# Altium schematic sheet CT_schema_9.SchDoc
size 254 x 194 mm
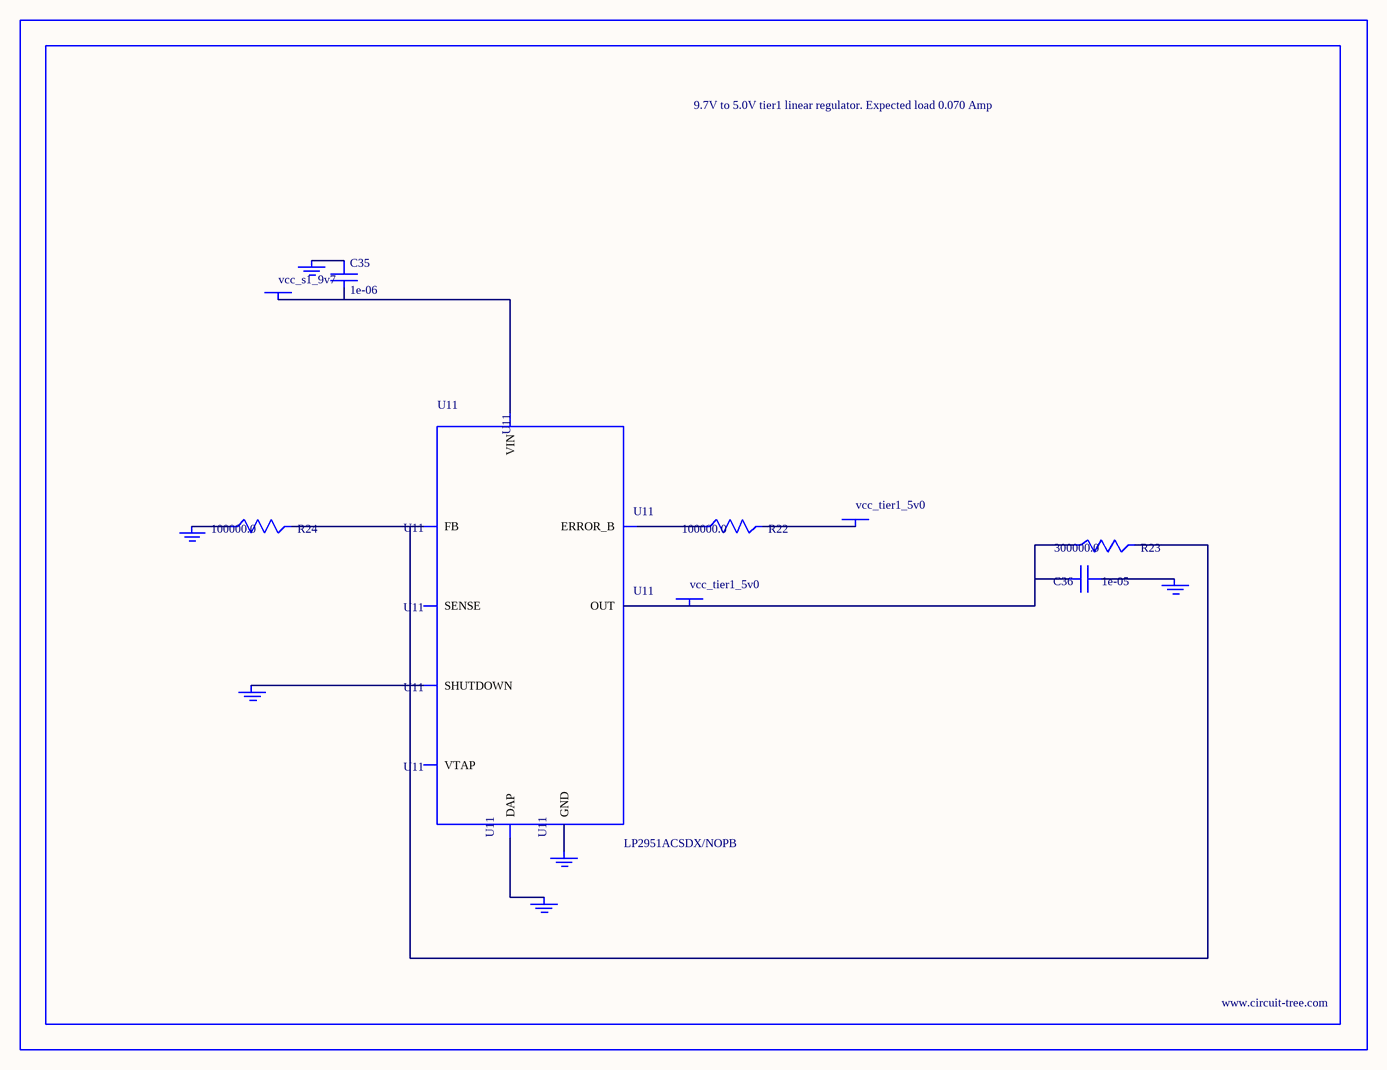
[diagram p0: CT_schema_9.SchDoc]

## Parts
BORDER8  (no value)
C35  1e-06  [C0603]
C36  1e-05  [C1210]
GND_INSTANCE_8_0  (no value)
GND_INSTANCE_8_1  (no value)
GND_INSTANCE_8_2  (no value)
GND_INSTANCE_8_3  (no value)
GND_INSTANCE_8_4  (no value)
GND_INSTANCE_8_5  (no value)
POWER_INSTANCE_8_0  vcc_tier1_5v0
POWER_INSTANCE_8_1  vcc_s1_9v7
POWER_INSTANCE_8_2  vcc_tier1_5v0
R22  100000.0  [R0603]
R23  300000.0  [R0603]
R24  100000.0  [R0603]
U11  LP2951ACSDX/NOPB  [WSON-8]

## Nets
NetC35_1: C35.1 GND_INSTANCE_8_3.0(GND)
NetC35_2: C35.2 POWER_INSTANCE_8_1.0(PWR) U11.8(VIN)
NetC36_1: C36.1 GND_INSTANCE_8_0.0(GND)
NetC36_2: C36.2 POWER_INSTANCE_8_2.0(PWR) R23.1 U11.1(OUT)
NetGND_INSTANCE_8_1_0: GND_INSTANCE_8_1.0(GND) U11.3(SHUTDOWN)
NetGND_INSTANCE_8_2_0: GND_INSTANCE_8_2.0(GND) R24.1
NetGND_INSTANCE_8_4_0: GND_INSTANCE_8_4.0(GND) U11.PAD(DAP)
NetGND_INSTANCE_8_5_0: GND_INSTANCE_8_5.0(GND) U11.4(GND)
NetPOWER_INSTANCE_8_0_0: POWER_INSTANCE_8_0.0(PWR) R22.2
NetR22_1: R22.1 U11.5(ERROR_B)
NetR23_2: R23.2 R24.2 U11.7(FB)

Not connected (* = marked no-connect by the designer): U11 2(SENSE) 6(VTAP)

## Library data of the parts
BORDER8 = BORDER_PAGE8
C35 = C0603C105K3RACTU
C36 = GRM32DR61E106MA12L
GND_INSTANCE_8_0-GND_INSTANCE_8_5 = GND
POWER_INSTANCE_8_0-POWER_INSTANCE_8_2 = PWR
R22 R24 = RC0603JR-07100KL
R23 = RC0603JR-07300KL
